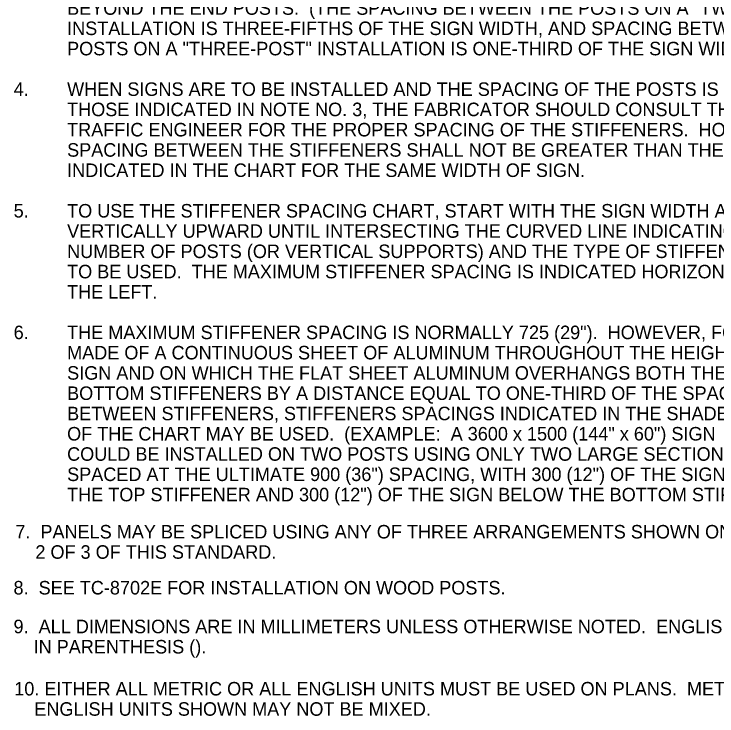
# Model space of a CAD drawing. Extents: x 650495 to 652241, y 298458 to 299646.
# Drawn here: x 651065.8 to 651221.8, y 299389.4 to 299545.2 of the extents above; entities that cross this region are included whole.
import ezdxf

# ---------------------------------------------------------------- set-up
doc = ezdxf.new("R2010")
doc.units = 0
doc.layers.add('2', color=7, linetype='Continuous')

msp = doc.modelspace()

# ---------------------------------------------------------------- texts
at = {"layer": '2'}
for s, height, p in [('BEYOND THE END POSTS.  (THE SPACING BETWEEN THE POSTS ON A "TWO-POST" ', 3, (651077.56, 299545)), ('INSTALLATION IS THREE-FIFTHS OF THE SIGN WIDTH, AND SPACING BETWEEN THE ', 3, (651077.56, 299540.5)), ('POSTS ON A "THREE-POST" INSTALLATION IS ONE-THIRD OF THE SIGN WIDTH.)', 3, (651077.56, 299536)), ('4.  ', 3, (651065.69, 299527)), ('WHEN SIGNS ARE TO BE INSTALLED AND THE SPACING OF THE POSTS IS OTHER THAN ', 3, (651077.56, 299527)), ('THOSE INDICATED IN NOTE NO. 3, THE FABRICATOR SHOULD CONSULT THE DISTRICT ', 3, (651077.56, 299522.5)), ('TRAFFIC ENGINEER FOR THE PROPER SPACING OF THE STIFFENERS.  HOWEVER, THE ', 3, (651077.56, 299518)), ('SPACING BETWEEN THE STIFFENERS SHALL NOT BE GREATER THAN THE SPACING ', 3, (651077.56, 299513.5)), ('INDICATED IN THE CHART FOR THE SAME WIDTH OF SIGN.', 3, (651077.56, 299509)), ('5.  ', 2.999, (651065.69, 299500)), ('TO USE THE STIFFENER SPACING CHART, START WITH THE SIGN WIDTH AND GO', 3, (651077.56, 299500)), ('VERTICALLY UPWARD UNTIL INTERSECTING THE CURVED LINE INDICATING THE PROPER', 3, (651077.56, 299495.5)), ('NUMBER OF POSTS (OR VERTICAL SUPPORTS) AND THE TYPE OF STIFFENER SECTION', 3, (651077.56, 299491)), ('TO BE USED.  THE MAXIMUM STIFFENER SPACING IS INDICATED HORIZONTALLY TO', 3, (651077.56, 299486.5)), ('THE LEFT.', 3, (651077.56, 299482)), ('6.  ', 2.999, (651065.69, 299473)), ('THE MAXIMUM STIFFENER SPACING IS NORMALLY 725 (29").  HOWEVER, FOR SIGNS', 3, (651077.56, 299473)), ('MADE OF A CONTINUOUS SHEET OF ALUMINUM THROUGHOUT THE HEIGHT OF THE ', 3, (651077.56, 299468.5)), ('SIGN AND ON WHICH THE FLAT SHEET ALUMINUM OVERHANGS BOTH THE TOP AND ', 3, (651077.56, 299464)), ('BOTTOM STIFFENERS BY A DISTANCE EQUAL TO ONE-THIRD OF THE SPACING', 3, (651077.56, 299459.5)), ('BETWEEN STIFFENERS, STIFFENERS SPACINGS INDICATED IN THE SHADED PORTION', 3, (651077.56, 299455)), ('OF THE CHART MAY BE USED.  (EXAMPLE:  A 3600 x 1500 (144" x 60") SIGN ', 3, (651077.56, 299450.5)), ('COULD BE INSTALLED ON TWO POSTS USING ONLY TWO LARGE SECTION STIFFENERS ', 3, (651077.56, 299446)), ('SPACED AT THE ULTIMATE 900 (36") SPACING, WITH 300 (12") OF THE SIGN ABOVE', 3, (651077.56, 299441.5)), ('THE TOP STIFFENER AND 300 (12") OF THE SIGN BELOW THE BOTTOM STIFFENER.)', 3, (651077.56, 299437)), ('7.  PANELS MAY BE SPLICED USING ANY OF THREE ARRANGEMENTS SHOWN ON SHEET', 3, (651066.06, 299428.75)), ('    2 OF 3 OF THIS STANDARD.', 3, (651066.06, 299424.25)), ('8.  SEE TC-8702E FOR INSTALLATION ON WOOD POSTS.', 3, (651065.66, 299416.32)), ('9.  ALL DIMENSIONS ARE IN MILLIMETERS UNLESS OTHERWISE NOTED.  ENGLISH UNITS', 3, (651065.66, 299407.72)), ('    IN PARENTHESIS ().', 3, (651065.66, 299403.22)), ('10. EITHER ALL METRIC OR ALL ENGLISH UNITS MUST BE USED ON PLANS.  METRIC AND', 3, (651065.82, 299393.9)), ('    ENGLISH UNITS SHOWN MAY NOT BE MIXED.', 3, (651065.82, 299389.4))]:
    msp.add_text(s, height=height, dxfattribs=at).set_placement(p)

doc.saveas('drawing.dxf')
